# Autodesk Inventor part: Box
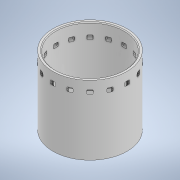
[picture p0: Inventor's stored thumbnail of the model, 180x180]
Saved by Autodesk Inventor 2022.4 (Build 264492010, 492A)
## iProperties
Created: 2022-12
Part Number: Box
Material: Generic
Document SubType Name: Modeling
Designer: tmass
Density: 1 g/cm^3
Appearance: Default
Author: tmass
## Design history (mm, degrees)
sketch "Sketch1"
  geometry: C1 r 42.025 at (0, 0); C2 r 45.525 at (0, 0); 1 further point
  constraints: 2 centre point, 2 coincident
  dimensions: "d0" = 84.05 diameter of C1; "d38" = 3.5 radial gap between concentric circles of C1 C2
extrude "Extrusion1" new body sketch "Sketch1" distance "d2" = 85; taper "d3" = 0 deg
sketch "Sketch2"
  geometry: L1 (45.525, 0)-(45.525, 85) reference; L2 (42.025, 85)-(42.025, 0) reference; L3 (45.525, 85)-(-45.525, 85) reference; L4 (42.025, 71.5)-(45.525, 75); L5 (42.025, 66.5)-(45.525, 70); L6 (42.025, 71.5)-(42.025, 66.5); L7 (45.525, 70)-(45.525, 75); L8 (42.025, 71.5)-(37.064, 66.539); L9 (39.332, 63.807)-(42.025, 66.5); L10 (37.064, 66.539)-(39.332, 63.807); 2 further points
  constraints: 14 end point, 3 point on line, 2 parallel, 1 collinear
  dimensions: "d4" = 5 distance of L5.start L4.start; "d5" = 5 distance of L4.end L5.end; "d8" = 45 deg angle of L2 L5; "d9" = 10 distance of L4.end L1.end
extrude "Extrusion3" cut sketch "Sketch2" stored distance "d10" = 6; taper "d11" = 0 deg
fillet "Fillet1" dims "d12" = 1
chamfer "Chamfer1" distance "d16" = 1; stored, may be unused: second distance "d17" = 2, angle "d18" = 45 deg
pattern_circular "Circular Pattern2" dims angle "d20" = 360 deg
workplane "Work Plane1"
body "Solid1"
other parameters: "d24" = 43
